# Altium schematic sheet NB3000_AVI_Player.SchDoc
size B
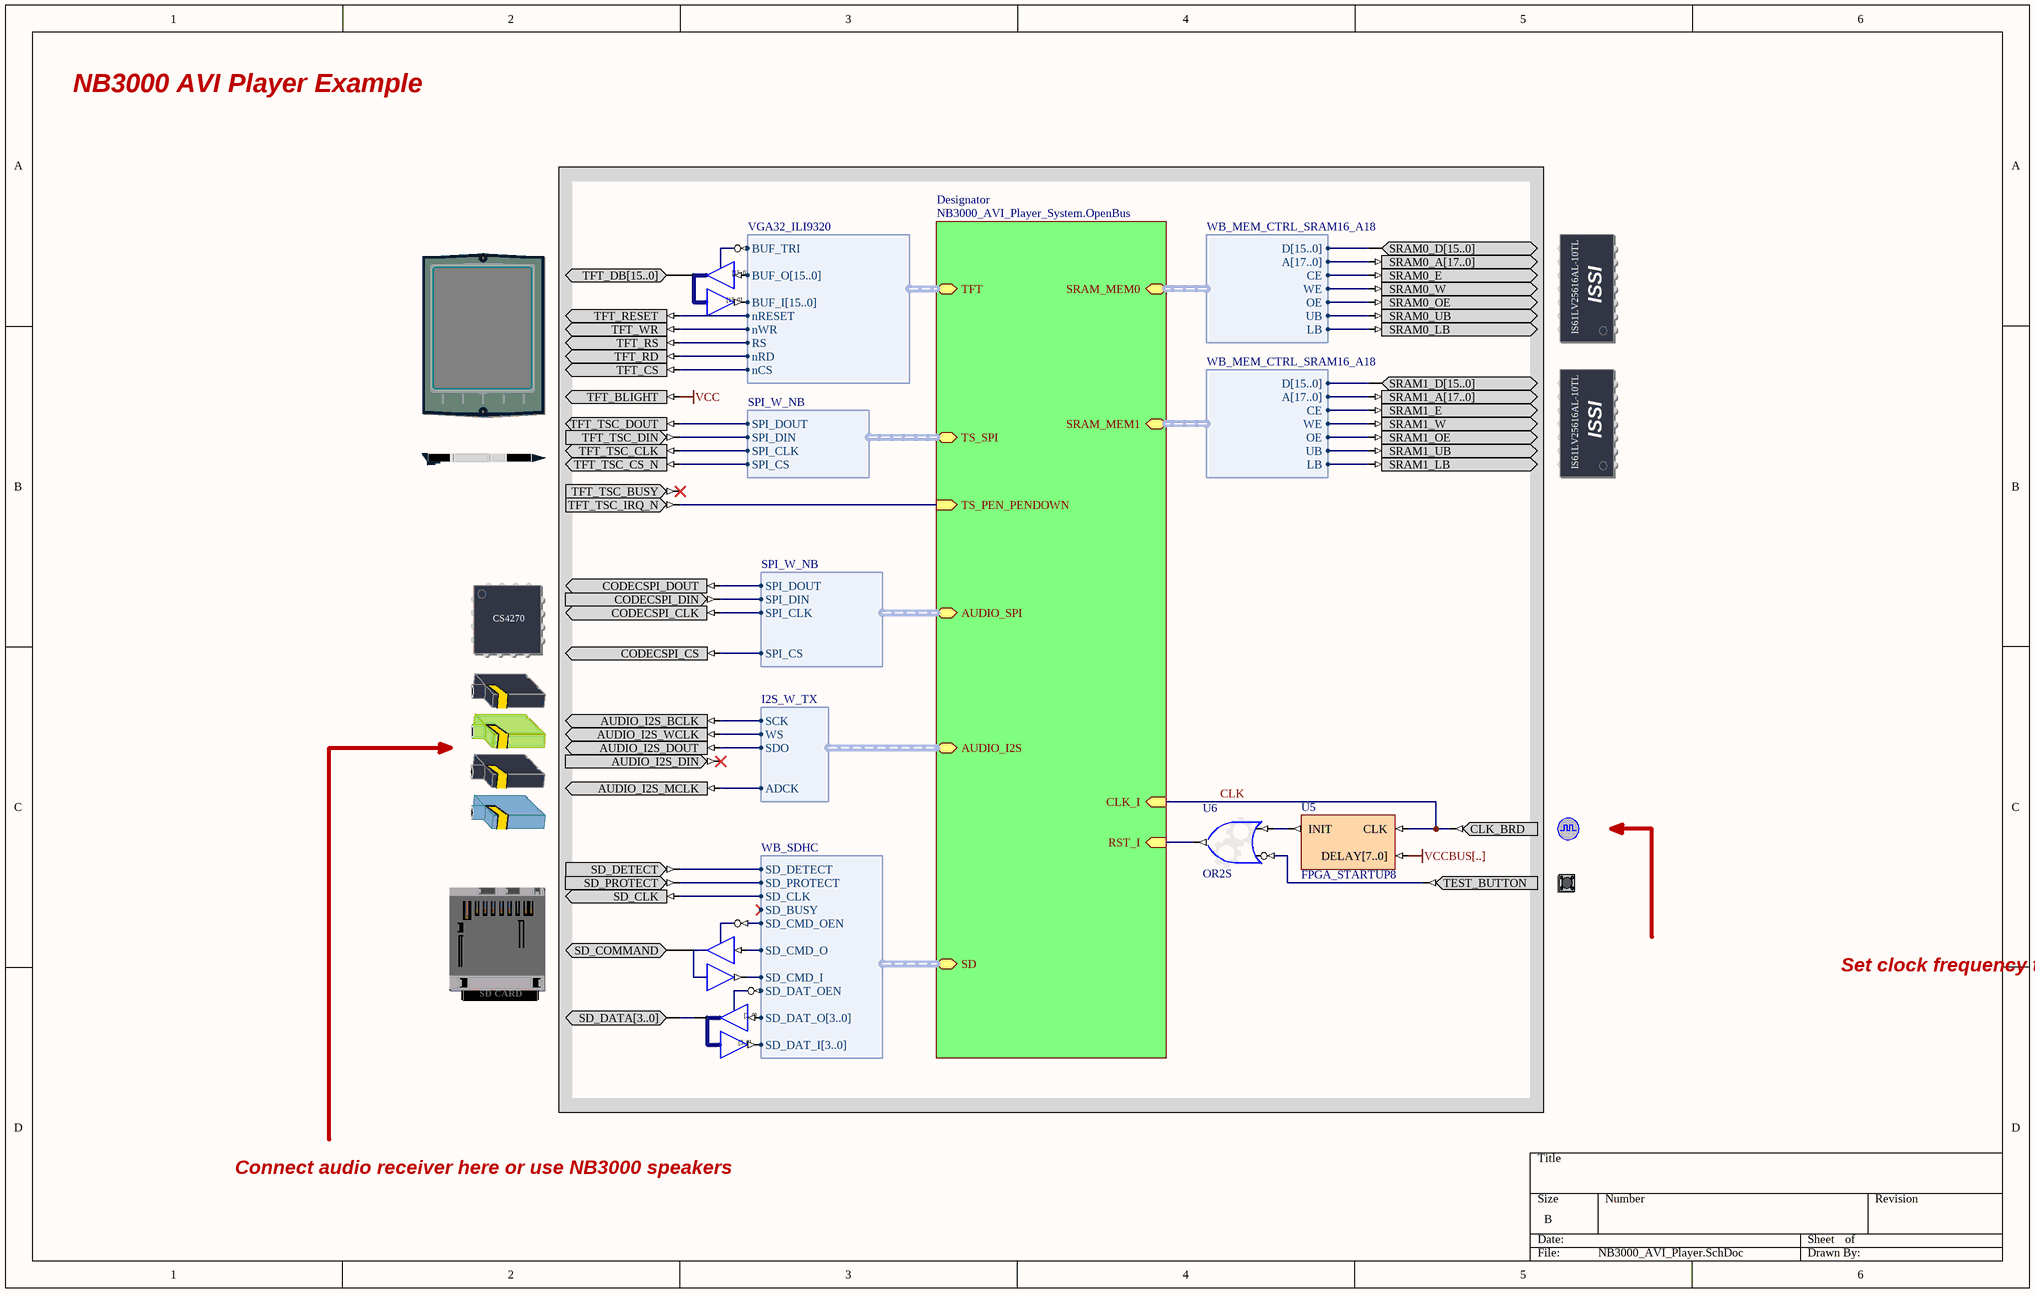
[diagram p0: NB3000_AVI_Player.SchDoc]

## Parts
(Parts that share a designator on the sheet are numbered #1, #2 ... from top to bottom, then left to right.)
?#1  SRAM0  (value not drawn)
?#2  TFT_LCD  (value not drawn)
?#3  SRAM1  (value not drawn)
?#4  TOUCH_SCREEN_PEN  (value not drawn)
?#5  AUDIO_CODEC_CTRL  (value not drawn)
?#6  AUDIO_CODEC  (value not drawn)
?#7  CLOCK_BOARD  (value not drawn)
?#8  SD_HOST  (value not drawn)
?#9  TEST_BUTTON  (value not drawn)
IOBUF_CMD  IOBUF  (value not drawn)
IOBUF_DATA  IOBUF4B  (value not drawn)
U5  FPGA_STARTUP8
U6  OR2S
UIBUF_TFT  IOBUF16B  (value not drawn)

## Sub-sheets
Designator = NB3000_AVI_Player_System.OpenBus: CLK_I (in), RST_I (in), SRAM_MEM0 (harness WB_MEM_CTRL_SRAM16_A18), SRAM_MEM1 (harness WB_MEM_CTRL_SRAM16_A18), TFT (harness VGA32_ILI9320), AUDIO_SPI (harness SPI_W_NB), TS_SPI (harness SPI_W_NB), TS_PEN_PENDOWN (in), AUDIO_I2S (harness I2S_W_TX), SD (harness WB_SDHC)

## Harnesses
WB_MEM_CTRL_SRAM16_A18: D[15..0], A[17..0], CE, WE, OE, UB, LB
SPI_W_NB: SPI_DOUT, SPI_DIN, SPI_CLK, SPI_CS
VGA32_ILI9320: BUF_TRI, BUF_O[15..0], BUF_I[15..0], nRESET, nWR, RS, nRD, nCS
I2S_W_TX: SCK, WS, SDO, ADCK
WB_SDHC: SD_DETECT, SD_PROTECT, SD_CLK, SD_BUSY, SD_CMD_OEN, SD_CMD_O, SD_CMD_I, SD_DAT_OEN, SD_DAT_O[3..0], SD_DAT_I[3..0]

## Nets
VCC: ?#2.TFT_BLIGHT
VCCBUS[..]: U5.DELAY[7..0]
CLK: ?#7.CLK_BRD U5.CLK ; sheet Designator/CLK_I
Net?#1_SRAM0_E: ?#1.SRAM0_E ; sheet Designator/SRAM_MEM0.CE
Net?#1_SRAM0_LB: ?#1.SRAM0_LB ; sheet Designator/SRAM_MEM0.LB
Net?#1_SRAM0_OE: ?#1.SRAM0_OE ; sheet Designator/SRAM_MEM0.OE
Net?#1_SRAM0_UB: ?#1.SRAM0_UB ; sheet Designator/SRAM_MEM0.UB
Net?#1_SRAM0_W: ?#1.SRAM0_W ; sheet Designator/SRAM_MEM0.WE
Net?#2_TFT_CS: ?#2.TFT_CS ; sheet Designator/TFT.nCS
Net?#2_TFT_DB[15..0]: ?#2.TFT_DB[15..0] UIBUF_TFT.IO[15..0]
Net?#2_TFT_RD: ?#2.TFT_RD ; sheet Designator/TFT.nRD
Net?#2_TFT_RESET: ?#2.TFT_RESET ; sheet Designator/TFT.nRESET
Net?#2_TFT_RS: ?#2.TFT_RS ; sheet Designator/TFT.RS
Net?#2_TFT_WR: ?#2.TFT_WR ; sheet Designator/TFT.nWR
Net?#3_SRAM1_E: ?#3.SRAM1_E ; sheet Designator/SRAM_MEM1.CE
Net?#3_SRAM1_LB: ?#3.SRAM1_LB ; sheet Designator/SRAM_MEM1.LB
Net?#3_SRAM1_OE: ?#3.SRAM1_OE ; sheet Designator/SRAM_MEM1.OE
Net?#3_SRAM1_UB: ?#3.SRAM1_UB ; sheet Designator/SRAM_MEM1.UB
Net?#3_SRAM1_W: ?#3.SRAM1_W ; sheet Designator/SRAM_MEM1.WE
Net?#4_TFT_TSC_CLK: ?#4.TFT_TSC_CLK ; sheet Designator/TS_SPI.SPI_CLK
Net?#4_TFT_TSC_CS_N: ?#4.TFT_TSC_CS_N ; sheet Designator/TS_SPI.SPI_CS
Net?#4_TFT_TSC_DIN: ?#4.TFT_TSC_DIN ; sheet Designator/TS_SPI.SPI_DIN
Net?#4_TFT_TSC_DOUT: ?#4.TFT_TSC_DOUT ; sheet Designator/TS_SPI.SPI_DOUT
Net?#4_TFT_TSC_IRQ_N: ?#4.TFT_TSC_IRQ_N ; sheet Designator/TS_PEN_PENDOWN
Net?#5_CODECSPI_CLK: ?#5.CODECSPI_CLK ; sheet Designator/AUDIO_SPI.SPI_CLK
Net?#5_CODECSPI_CS: ?#5.CODECSPI_CS ; sheet Designator/AUDIO_SPI.SPI_CS
Net?#5_CODECSPI_DIN: ?#5.CODECSPI_DIN ; sheet Designator/AUDIO_SPI.SPI_DIN
Net?#5_CODECSPI_DOUT: ?#5.CODECSPI_DOUT ; sheet Designator/AUDIO_SPI.SPI_DOUT
Net?#6_AUDIO_I2S_BCLK: ?#6.AUDIO_I2S_BCLK ; sheet Designator/AUDIO_I2S.SCK
Net?#6_AUDIO_I2S_DOUT: ?#6.AUDIO_I2S_DOUT ; sheet Designator/AUDIO_I2S.SDO
Net?#6_AUDIO_I2S_MCLK: ?#6.AUDIO_I2S_MCLK ; sheet Designator/AUDIO_I2S.ADCK
Net?#6_AUDIO_I2S_WCLK: ?#6.AUDIO_I2S_WCLK ; sheet Designator/AUDIO_I2S.WS
Net?#8_SD_CLK: ?#8.SD_CLK ; sheet Designator/SD.SD_CLK
Net?#8_SD_COMMAND: ?#8.SD_COMMAND IOBUF_CMD.IO
Net?#8_SD_DETECT: ?#8.SD_DETECT ; sheet Designator/SD.SD_DETECT
Net?#8_SD_PROTECT: ?#8.SD_PROTECT ; sheet Designator/SD.SD_PROTECT
Net?#9_TEST_BUTTON: ?#9.TEST_BUTTON U6.I1
NetIOBUF_CMD_I: IOBUF_CMD.I ; sheet Designator/SD.SD_CMD_O
NetIOBUF_CMD_O: IOBUF_CMD.O ; sheet Designator/SD.SD_CMD_I
NetIOBUF_CMD_T: IOBUF_CMD.T ; sheet Designator/SD.SD_CMD_OEN
NetIOBUF_DATA_T: IOBUF_DATA.T ; sheet Designator/SD.SD_DAT_OEN
NetU5_INIT: U5.INIT U6.I0
NetU6_O: U6.O ; sheet Designator/RST_I
NetUIBUF_TFT_T: UIBUF_TFT.T ; sheet Designator/TFT.BUF_TRI

Not connected (* = marked no-connect by the designer): ?#1 SRAM0_A[17..0] SRAM0_D[15..0]; ?#3 SRAM1_A[17..0] SRAM1_D[15..0]; ?#4 TFT_TSC_BUSY*; ?#6 AUDIO_I2S_DIN*; ?#8 SD_DATA[3..0]; IOBUF_DATA I[3..0] IO[3..0] O[3..0]; UIBUF_TFT I[15..0] O[15..0]

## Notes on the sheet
- NB3000 AVI Player Example
- Set clock frequency to 50 MHz
- Connect audio receiver here or use NB3000 speakers

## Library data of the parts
?#1 = SRAM0: Free Static RAM - Daughterboard; PortComponent: True
?#2 = TFT_LCD: TFT LCD Panel; PortComponent: True
?#3 = SRAM1: Free Static RAM - Daughterboard; PortComponent: True
?#4 = TFT_PEN: Touch Screen Pen Control; PortComponent: True
?#5 = AUDIO_CODEC_CTRL: Audio Codec Control; PortComponent: True
?#6 = AUDIO_CODEC: Audio Codec; PortComponent: True; IncludeInDSF: AUDIO_CS4270
?#7 = CLOCK_BOARD: Global System Clock Supply; PortComponent: True
?#8 = SD_HOST: Secure Digital Card Host; PortComponent: True
?#9 = TEST_BUTTON: Test / Reset Button; PortComponent: True
IOBUF_CMD = IOBUF: Input/Output Buffer; Enable: Low; Control: Common Control T; ArchiveName: GENERIC; VHDLIB_SIM: GENERIC_LIB
IOBUF_DATA = IOBUF4B: 4-Bit Input/Output Buffer, Bus Version; SubClass: IOBUF; Enable: Low; Control: Common Control T; PortSize: 4; ArchiveName: GENERIC; VHDLIB_SIM: GENERIC_LIB
U5 = FPGA_STARTUP8: FPGA Startup With 8 Bit Delay
U6 = GATE: Configurable Generic Gate; ConfiguratorName: GENERIC_GATE; ConfigurationParameters: {}Version[1.0]{}GateKind[OR]{}BusInput[False]{}GateInputType[Bit]{}GateOutputOption[Normal]{}BusWidth[8]{}RegisterOutputs[False]{}NegativeClockEdge[False]{}InputCount[2]{}InputInvert0[False]{}InputInvert1[True]{}
UIBUF_TFT = IOBUF16B: 16-Bit Input/Output Buffer, Bus Version; SubClass: IOBUF; Enable: Low; Control: Common Control T; PortSize: 16; ArchiveName: GENERIC; VHDLIB_SIM: GENERIC_LIB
